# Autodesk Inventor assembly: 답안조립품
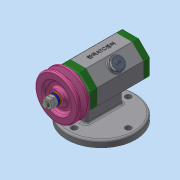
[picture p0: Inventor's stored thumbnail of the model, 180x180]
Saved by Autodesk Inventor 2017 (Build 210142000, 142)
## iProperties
Part Number: 답안조립품
Material: 일반
Document SubType Name: Assembly
Designer: 222
Author: 222
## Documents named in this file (14)
- C:\Users\222\Desktop\710204V1024\답안조립품.iam
- C:\Users\222\Desktop\710204V1024\본체.ipt
- C:\Users\222\Desktop\710204V1024\베어링 15 x 32 x 9.ipt
- C:\Users\222\Desktop\710204V1024\뒤커버.ipt
- C:\Users\222\Desktop\710204V1024\앞커버.ipt
- C:\Users\222\Desktop\710204V1024\오일 실 15 25 7.ipt
- C:\Users\222\Desktop\710204V1024\V벨트풀리.ipt
- C:\Users\222\Desktop\710204V1024\축.ipt
- C:\Users\222\Desktop\710204V1024\키 3 x 3 x 12.ipt
- C:\Users\222\Desktop\710204V1024\너트 M8.ipt
- C:\Users\222\Desktop\710204V1024\스프링와셔 8.ipt
- C:\Users\222\Desktop\710204V1024\와셔 8x17.ipt
- C:\Users\222\Desktop\710204V1024\고무캡.ipt
- C:\Users\222\Desktop\710204V1024\볼트 M4 x 12.ipt
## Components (2 placed, 2 different names)
1. V벨트풀리:1 — 각도:3
2. 고무캡:1
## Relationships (1: Angle 1)
- 각도:3 [Angle]: V벨트풀리:1
